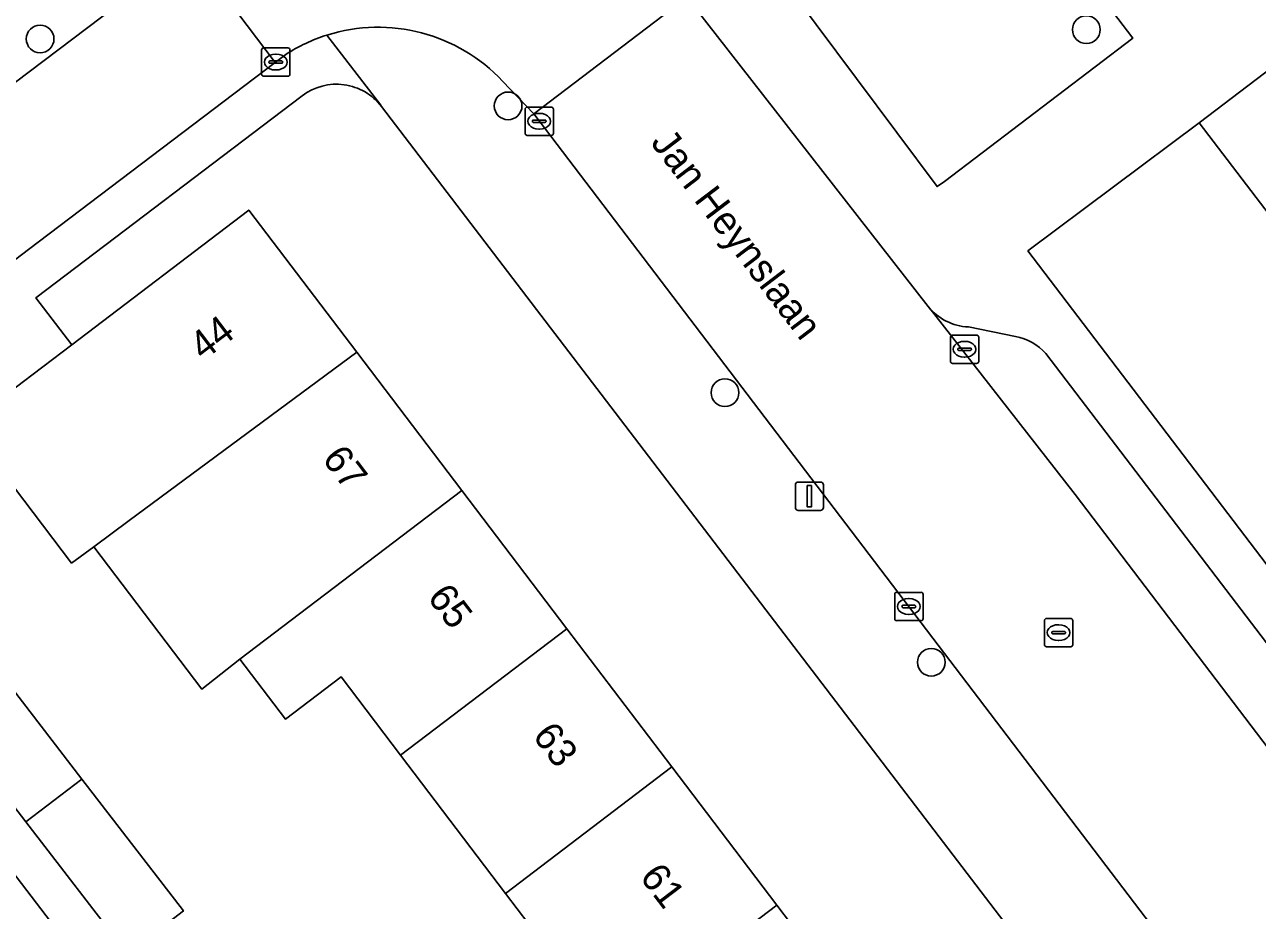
# Model space of a CAD drawing. Extents: x 160030 to 160839, y 385325 to 386450.
# Drawn here: x 160565.67 to 160609.22, y 385568.33 to 385599.6 of the extents above; entities that cross this region are included whole.
import ezdxf

# ---------------------------------------------------------------- set-up
doc = ezdxf.new("R2010")
doc.units = 0
for name, color, linetype in [('IMGEO_Boom', 7, 'Continuous'), ('IMGEO_Erf', 7, 'Continuous'), ('IMGEO_Groenvoorziening', 7, 'Continuous'), ('IMGEO_Kolk', 7, 'Continuous'), ('IMGEO_Lichtmast', 7, 'Continuous'), ('IMGEO_Openbare_ruimte_label', 7, 'Continuous'), ('IMGEO_Pand', 7, 'Continuous'), ('IMGEO_Pand_nummerreeks', 7, 'Continuous'), ('IMGEO_Parkeervlak_open', 7, 'Continuous'), ('IMGEO_Rijbaan_lokaal_open', 7, 'Continuous'), ('IMGEO_Rioolput', 7, 'Continuous'), ('IMGEO_Voetpad_open', 7, 'Continuous')]:
    doc.layers.add(name, color=color, linetype=linetype)

msp = doc.modelspace()

# ---------------------------------------------------------------- linework, layer by layer
at = {"layer": 'IMGEO_Boom'}
for centre in [(160603.18, 385599.427), (160566.216, 385599.099), (160582.75, 385596.735), (160590.41, 385586.607), (160597.7, 385577.088)]:
    msp.add_circle(centre, 0.489, dxfattribs=at)
at = {"layer": 'IMGEO_Erf'}
for points in [[(160575.476, 385597.093), (160566.063, 385589.953), (160567.331, 385588.298), (160573.589, 385593.054), (160577.403, 385588.035), (160581.113, 385583.153), (160584.823, 385578.272), (160588.533, 385573.391), (160592.243, 385568.509), (160595.953, 385563.627), (160599.662, 385558.746), (160603.372, 385553.865), (160607.082, 385548.983), (160610.81, 385544.077), (160614.502, 385539.22), (160618.212, 385534.339), (160621.922, 385529.457), (160625.631, 385524.577), (160629.447, 385519.555), (160627.058, 385517.74)], [(160634.366, 385522.885), (160630.389, 385528.503), (160578.279, 385596.709)], [(160611.004, 385591.106), (160607.169, 385596.142), (160601.116, 385591.616), (160615.06, 385573.306)], [(160595.425, 385547.827), (160591.715, 385552.708), (160592.087, 385552.99), (160593.788, 385554.282), (160590.079, 385559.164), (160586.369, 385564.045), (160582.659, 385568.927), (160578.949, 385573.808), (160576.846, 385576.575), (160574.882, 385575.082), (160573.275, 385577.197), (160571.926, 385576.142), (160568.108, 385581.165), (160567.326, 385580.587), (160563.613, 385585.473)], [(160565.202, 385576.196), (160567.695, 385572.958), (160571.278, 385568.306)]]:
    msp.add_lwpolyline(points, dxfattribs=at)
msp.add_arc((160576.686, 385595.501), 1.999, 37.1667, 127.2318, dxfattribs=at)
at = {"layer": 'IMGEO_Groenvoorziening'}
msp.add_lwpolyline([(160599.025, 385606.736), (160592.457, 385601.711), (160592.212, 385601.528), (160597.904, 385593.887), (160598.172, 385594.067), (160604.818, 385599.124)], close=True, dxfattribs=at)
at = {"layer": 'IMGEO_Kolk'}
for p, q in [((160574.042, 385597.856), (160574.042, 385598.708)), ((160574.117, 385598.782), (160574.969, 385598.782)), ((160574.53, 385598.562), (160574.555, 385598.562)), ((160575.043, 385598.708), (160575.043, 385597.856)), ((160574.301, 385598.276), (160574.301, 385598.288)), ((160574.739, 385598.239), (160574.341, 385598.239)), ((160574.344, 385598.325), (160574.742, 385598.325)), ((160574.785, 385598.288), (160574.785, 385598.276)), ((160574.969, 385597.782), (160574.117, 385597.782)), ((160574.553, 385598.002), (160574.528, 385598.002)), ((160583.349, 385595.765), (160583.349, 385596.617)), ((160583.424, 385596.691), (160584.276, 385596.691)), ((160583.837, 385596.471), (160583.862, 385596.471)), ((160584.35, 385596.617), (160584.35, 385595.765)), ((160583.608, 385596.185), (160583.608, 385596.197)), ((160584.046, 385596.148), (160583.648, 385596.148)), ((160583.651, 385596.234), (160584.049, 385596.234)), ((160584.092, 385596.197), (160584.092, 385596.185)), ((160584.276, 385595.691), (160583.424, 385595.691)), ((160583.86, 385595.911), (160583.835, 385595.911)), ((160598.376, 385587.713), (160598.376, 385588.565)), ((160598.451, 385588.639), (160599.303, 385588.639)), ((160599.377, 385588.565), (160599.377, 385587.713)), ((160598.635, 385588.133), (160598.635, 385588.145)), ((160599.073, 385588.096), (160598.675, 385588.096)), ((160598.678, 385588.182), (160599.076, 385588.182)), ((160598.864, 385588.419), (160598.889, 385588.419)), ((160599.119, 385588.145), (160599.119, 385588.133)), ((160598.887, 385587.859), (160598.862, 385587.859)), ((160599.303, 385587.639), (160598.451, 385587.639)), ((160596.407, 385578.63), (160596.407, 385579.482)), ((160596.482, 385579.556), (160597.334, 385579.556)), ((160597.408, 385579.482), (160597.408, 385578.63)), ((160596.666, 385579.05), (160596.666, 385579.062)), ((160597.104, 385579.013), (160596.706, 385579.013)), ((160596.709, 385579.099), (160597.107, 385579.099)), ((160596.895, 385579.336), (160596.92, 385579.336)), ((160597.15, 385579.062), (160597.15, 385579.05)), ((160597.334, 385578.556), (160596.482, 385578.556)), ((160596.918, 385578.776), (160596.893, 385578.776))]:
    msp.add_line(p, q, dxfattribs=at)
for points in [[(160574.042, 385597.856), (160574.042, 385598.708)], [(160574.117, 385598.782), (160574.969, 385598.782)], [(160575.043, 385598.708), (160575.043, 385597.856)], [(160574.969, 385597.782), (160574.117, 385597.782)], [(160583.349, 385595.765), (160583.349, 385596.617)], [(160583.424, 385596.691), (160584.276, 385596.691)], [(160584.35, 385596.617), (160584.35, 385595.765)], [(160584.276, 385595.691), (160583.424, 385595.691)], [(160598.376, 385587.713), (160598.376, 385588.565)], [(160598.451, 385588.639), (160599.303, 385588.639)], [(160599.377, 385588.565), (160599.377, 385587.713)], [(160599.303, 385587.639), (160598.451, 385587.639)], [(160596.407, 385578.63), (160596.407, 385579.482)], [(160596.482, 385579.556), (160597.334, 385579.556)], [(160597.408, 385579.482), (160597.408, 385578.63)], [(160597.334, 385578.556), (160596.482, 385578.556)]]:
    msp.add_lwpolyline(points, dxfattribs=at)
for centre, radius, start, end in [((160574.119, 385598.706), 0.0765, 91.552, 178.448), ((160574.119, 385598.706), 0.0765, 91.552, 178.448), ((160574.967, 385598.706), 0.0765, 1.552, 88.448), ((160574.967, 385598.706), 0.0765, 1.552, 88.448), ((160574.341, 385598.285), 0.0403, 85.8775, 175.7526), ((160574.338, 385598.275), 0.0366, 178.938, 274.7102), ((160574.742, 385598.282), 0.043, 264.8664, 352.4533), ((160574.746, 385598.287), 0.0386, 1.7309, 96.639), ((160574.119, 385597.858), 0.0765, 181.552, 268.448), ((160574.119, 385597.858), 0.0765, 181.552, 268.448), ((160574.967, 385597.858), 0.0765, 271.552, 358.448), ((160574.967, 385597.858), 0.0765, 271.552, 358.448), ((160583.426, 385596.615), 0.0765, 91.552, 178.448), ((160583.426, 385596.615), 0.0765, 91.552, 178.448), ((160584.274, 385596.615), 0.0765, 1.552, 88.448), ((160584.274, 385596.615), 0.0765, 1.552, 88.448), ((160583.648, 385596.194), 0.0403, 85.8775, 175.7526), ((160583.645, 385596.184), 0.0366, 178.938, 274.7102), ((160584.049, 385596.191), 0.043, 264.8664, 352.4533), ((160584.053, 385596.196), 0.0386, 1.7309, 96.639), ((160583.426, 385595.767), 0.0765, 181.552, 268.448), ((160583.426, 385595.767), 0.0765, 181.552, 268.448), ((160584.274, 385595.767), 0.0765, 271.552, 358.448), ((160584.274, 385595.767), 0.0765, 271.552, 358.448), ((160598.453, 385588.563), 0.0765, 91.552, 178.448), ((160598.453, 385588.563), 0.0765, 91.552, 178.448), ((160599.301, 385588.563), 0.0765, 1.552, 88.448), ((160599.301, 385588.563), 0.0765, 1.552, 88.448), ((160598.675, 385588.142), 0.0403, 85.8775, 175.7526), ((160598.672, 385588.132), 0.0366, 178.938, 274.7102), ((160599.076, 385588.139), 0.043, 264.8664, 352.4533), ((160599.08, 385588.144), 0.0386, 1.7309, 96.639), ((160598.453, 385587.715), 0.0765, 181.552, 268.448), ((160598.453, 385587.715), 0.0765, 181.552, 268.448), ((160599.301, 385587.715), 0.0765, 271.552, 358.448), ((160599.301, 385587.715), 0.0765, 271.552, 358.448), ((160596.484, 385579.48), 0.0765, 91.552, 178.448), ((160596.484, 385579.48), 0.0765, 91.552, 178.448), ((160597.332, 385579.48), 0.0765, 1.552, 88.448), ((160597.332, 385579.48), 0.0765, 1.552, 88.448), ((160596.706, 385579.059), 0.0403, 85.8775, 175.7526), ((160596.703, 385579.049), 0.0366, 178.938, 274.7102), ((160597.107, 385579.056), 0.043, 264.8664, 352.4533), ((160597.111, 385579.061), 0.0386, 1.7309, 96.639), ((160596.484, 385578.632), 0.0765, 181.552, 268.448), ((160596.484, 385578.632), 0.0765, 181.552, 268.448), ((160597.332, 385578.632), 0.0765, 271.552, 358.448), ((160597.332, 385578.632), 0.0765, 271.552, 358.448)]:
    msp.add_arc(centre, radius, start, end, dxfattribs=at)
for centre, major_axis, ratio, start_param, end_param in [((160574.529, 385598.282), (-0.387, 0.002), 0.722429, 4.712389, 7.853982), ((160574.554, 385598.282), (-0.39, 0.002), 0.717154, 1.570796, 4.712389), ((160583.836, 385596.191), (-0.387, 0.002), 0.722429, 4.712389, 7.853982), ((160583.861, 385596.191), (-0.39, 0.002), 0.717154, 1.570796, 4.712389), ((160598.863, 385588.139), (-0.387, 0.002), 0.722429, 4.712389, 7.853982), ((160598.888, 385588.139), (-0.39, 0.002), 0.717154, 1.570796, 4.712389), ((160596.894, 385579.056), (-0.387, 0.002), 0.722429, 4.712389, 7.853982), ((160596.919, 385579.056), (-0.39, 0.002), 0.717154, 1.570796, 4.712389)]:
    msp.add_ellipse(centre, major_axis=major_axis, ratio=ratio, start_param=start_param, end_param=end_param, dxfattribs=at)
at = {"layer": 'IMGEO_Lichtmast'}
for p, q in [((160592.898, 385582.55), (160592.898, 385583.35)), ((160592.898, 385583.35), (160592.898, 385582.55)), ((160592.998, 385583.45), (160593.788, 385583.45)), ((160593.788, 385583.45), (160592.998, 385583.45)), ((160593.888, 385583.35), (160593.888, 385582.55)), ((160593.888, 385582.55), (160593.888, 385583.35)), ((160593.788, 385582.45), (160592.998, 385582.45)), ((160592.998, 385582.45), (160593.788, 385582.45))]:
    msp.add_line(p, q, dxfattribs=at)
msp.add_lwpolyline([(160593.318, 385583.325), (160593.468, 385583.325), (160593.468, 385582.575), (160593.318, 385582.575), (160593.318, 385583.325)], dxfattribs=at)
for centre, start, end in [((160592.998, 385583.35), 90, 180), ((160592.998, 385583.35), 90, 180), ((160593.788, 385583.35), 0, 90), ((160593.788, 385583.35), 360, 90), ((160592.998, 385582.55), 180, 270), ((160592.998, 385582.55), 180, 270), ((160593.788, 385582.55), 270, 0), ((160593.788, 385582.55), 270, 0)]:
    msp.add_arc(centre, 0.1, start, end, dxfattribs=at)
at = {"layer": 'IMGEO_Pand'}
for points in [[(160607.169, 385596.142), (160611.004, 385591.106), (160618.999, 385597.196), (160615.13, 385602.205), (160614.335, 385601.6)], [(160577.403, 385588.035), (160573.589, 385593.054), (160567.331, 385588.298), (160565.628, 385587.004), (160563.613, 385585.473), (160567.326, 385580.587), (160568.108, 385581.165), (160569.362, 385582.092)], [(160581.113, 385583.153), (160577.403, 385588.035), (160569.362, 385582.092), (160568.108, 385581.165), (160571.926, 385576.142), (160573.275, 385577.197)], [(160574.882, 385575.082), (160576.846, 385576.575), (160578.949, 385573.808), (160584.823, 385578.272), (160581.113, 385583.153), (160573.275, 385577.197)], [(160588.533, 385573.391), (160584.823, 385578.272), (160578.949, 385573.808), (160582.659, 385568.927)], [(160563.227, 385574.675), (160565.711, 385571.451), (160567.695, 385572.958), (160565.202, 385576.196)], [(160592.243, 385568.509), (160588.533, 385573.391), (160582.659, 385568.927), (160586.369, 385564.045)], [(160567.695, 385572.958), (160565.711, 385571.451), (160569.303, 385566.786), (160571.278, 385568.306)], [(160564.366, 385570.822), (160562.255, 385569.213), (160560.631, 385567.975), (160561.943, 385566.254), (160563.571, 385567.495), (160565.16, 385565.422), (160567.267, 385567.036)], [(160595.953, 385563.627), (160592.243, 385568.509), (160586.369, 385564.045), (160590.079, 385559.164)]]:
    msp.add_lwpolyline(points, close=True, dxfattribs=at)
at = {"layer": 'IMGEO_Parkeervlak_open'}
for points in [[(160597.595, 385589.647), (160597.787, 385589.401), (160602.781, 385583.007), (160639.01, 385535.418)], [(160600.679, 385588.587), (160599.012, 385588.929)], [(160615.901, 385569.421), (160613.783, 385572.222), (160601.753, 385587.99)]]:
    msp.add_lwpolyline(points, dxfattribs=at)
for centre, radius, start, end in [((160599.104, 385590.867), 1.941, 218.9687, 267.2882), ((160600.305, 385586.65), 1.973, 42.789, 79.0746)]:
    msp.add_arc(centre, radius, start, end, dxfattribs=at)
at = {"layer": 'IMGEO_Rijbaan_lokaal_open'}
for points in [[(160582.556, 385597.607), (160583.653, 385596.451), (160589.068, 385600.573), (160578.328, 385614.731)], [(160571.613, 385602.314), (160571.518, 385602.242), (160574.524, 385598.269), (160574.898, 385598.552)], [(160602.781, 385583.007), (160597.787, 385589.401), (160597.595, 385589.647), (160589.306, 385600.26), (160589.068, 385600.573), (160583.653, 385596.451), (160602.036, 385572.328), (160616.02, 385553.949), (160628.937, 385536.861), (160637.042, 385526.099)], [(160639.01, 385535.418), (160602.781, 385583.007)]]:
    msp.add_lwpolyline(points, dxfattribs=at)
msp.add_lwpolyline([(160565.014, 385591.06), (160565.606, 385591.507), (160565.804, 385591.667), (160574.524, 385598.269), (160571.518, 385602.242), (160538.386, 385577.219), (160541.415, 385573.243)], close=True, dxfattribs=at)
for centre, radius, start, end in [((160578.159, 385593.486), 6.026, 43.1442, 107.475), ((160578.182, 385593.447), 6.07, 107.5665, 122.7521)]:
    msp.add_arc(centre, radius, start, end, dxfattribs=at)
at = {"layer": 'IMGEO_Rioolput'}
for p, q in [((160601.698, 385577.707), (160601.698, 385578.559)), ((160601.773, 385578.633), (160602.625, 385578.633)), ((160602.699, 385578.559), (160602.699, 385577.707)), ((160601.957, 385578.127), (160601.957, 385578.139)), ((160602.395, 385578.09), (160601.997, 385578.09)), ((160602, 385578.176), (160602.398, 385578.176)), ((160602.186, 385578.413), (160602.211, 385578.413)), ((160602.441, 385578.139), (160602.441, 385578.127)), ((160602.209, 385577.853), (160602.184, 385577.853)), ((160602.625, 385577.633), (160601.773, 385577.633))]:
    msp.add_line(p, q, dxfattribs=at)
for points in [[(160601.698, 385577.707), (160601.698, 385578.559)], [(160601.773, 385578.633), (160602.625, 385578.633)], [(160602.699, 385578.559), (160602.699, 385577.707)], [(160602.625, 385577.633), (160601.773, 385577.633)]]:
    msp.add_lwpolyline(points, dxfattribs=at)
for centre, radius, start, end in [((160601.775, 385578.557), 0.0765, 91.552, 178.448), ((160601.775, 385578.557), 0.0765, 91.552, 178.448), ((160602.623, 385578.557), 0.0765, 1.552, 88.448), ((160602.623, 385578.557), 0.0765, 1.552, 88.448), ((160601.997, 385578.136), 0.0403, 85.8775, 175.7526), ((160601.994, 385578.126), 0.0366, 178.938, 274.7102), ((160602.398, 385578.133), 0.043, 264.8664, 352.4533), ((160602.402, 385578.138), 0.0386, 1.7309, 96.639), ((160601.775, 385577.709), 0.0765, 181.552, 268.448), ((160601.775, 385577.709), 0.0765, 181.552, 268.448), ((160602.623, 385577.709), 0.0765, 271.552, 358.448), ((160602.623, 385577.709), 0.0765, 271.552, 358.448)]:
    msp.add_arc(centre, radius, start, end, dxfattribs=at)
for centre, major_axis, ratio, start_param, end_param in [((160602.185, 385578.133), (-0.387, 0.002), 0.722429, 4.712389, 7.853982), ((160602.21, 385578.133), (-0.39, 0.002), 0.717154, 1.570796, 4.712389)]:
    msp.add_ellipse(centre, major_axis=major_axis, ratio=ratio, start_param=start_param, end_param=end_param, dxfattribs=at)
at = {"layer": 'IMGEO_Voetpad_open'}
for points in [[(160551.877, 385649.668), (160554.243, 385646.416), (160562.672, 385635.353), (160564.903, 385632.424), (160565.289, 385631.917), (160568.899, 385627.16), (160578.328, 385614.731), (160589.068, 385600.573), (160589.306, 385600.26), (160597.595, 385589.647)], [(160536.236, 385575.591), (160538.386, 385577.219), (160571.518, 385602.242), (160571.613, 385602.314)], [(160639.342, 385534.536), (160643.142, 385529.532), (160646.024, 385525.631), (160651.113, 385525.946), (160650.823, 385526.327), (160618.938, 385568.307), (160618.912, 385568.333), (160615.06, 385573.306), (160601.116, 385591.616), (160607.169, 385596.142), (160614.335, 385601.6)], [(160578.279, 385596.709), (160578.255, 385596.755), (160576.35, 385599.234)], [(160576.35, 385599.234), (160578.255, 385596.755), (160578.279, 385596.709), (160630.389, 385528.503), (160634.366, 385522.885)], [(160574.898, 385598.552), (160574.524, 385598.269), (160565.804, 385591.667), (160565.606, 385591.507), (160565.014, 385591.06)], [(160583.653, 385596.451), (160582.556, 385597.607)], [(160547.523, 385573.215), (160554.844, 385578.917), (160557.329, 385580.845), (160558.186, 385581.375), (160558.426, 385581.523), (160560.911, 385583.451), (160563.613, 385585.473), (160565.628, 385587.004), (160567.331, 385588.298), (160566.063, 385589.953), (160575.476, 385597.093)], [(160637.042, 385526.099), (160628.937, 385536.861), (160616.02, 385553.949), (160602.036, 385572.328), (160583.653, 385596.451)], [(160599.012, 385588.929), (160600.679, 385588.587)], [(160601.753, 385587.99), (160613.783, 385572.222), (160615.901, 385569.421), (160629.044, 385552.032), (160638.724, 385539.443)], [(160569.303, 385566.786), (160565.711, 385571.451), (160563.227, 385574.675)], [(160564.366, 385570.822), (160567.267, 385567.036)]]:
    msp.add_lwpolyline(points, dxfattribs=at)
msp.add_lwpolyline([(160604.818, 385599.124), (160598.172, 385594.067), (160597.904, 385593.887), (160592.212, 385601.528), (160592.457, 385601.711), (160599.025, 385606.736)], close=True, dxfattribs=at)
for centre, radius, start, end in [((160578.159, 385593.486), 6.026, 43.1442, 107.475), ((160578.182, 385593.447), 6.07, 107.5665, 122.7521), ((160576.686, 385595.501), 1.999, 37.1667, 127.2318), ((160599.104, 385590.867), 1.941, 218.9687, 267.2882), ((160600.305, 385586.65), 1.973, 42.789, 79.0746)]:
    msp.add_arc(centre, radius, start, end, dxfattribs=at)

# ---------------------------------------------------------------- texts
at = {"layer": 'IMGEO_Openbare_ruimte_label'}
msp.add_text('Jan Heynslaan', height=1, rotation=307.2823, dxfattribs=at).set_placement((160587.758, 385595.428))
at = {"layer": 'IMGEO_Pand_nummerreeks'}
for s, rotation, p in [('44', 37.2308, (160571.979, 385587.711)), ('67', 307.2363, (160576.151, 385584.263)), ('65', 307.2342, (160579.867, 385579.371)), ('63', 307.2342, (160583.585, 385574.48)), ('61', 307.2342, (160587.371, 385569.499))]:
    msp.add_text(s, height=1, rotation=rotation, dxfattribs=at).set_placement(p)

doc.saveas('drawing.dxf')
